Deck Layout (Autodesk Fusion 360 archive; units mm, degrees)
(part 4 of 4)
sketch "Filpper-Straight" plane through (0, 0, 0) normal (0, 0, 1) x axis (1, 0, 0)
  line L1 (-5.745, 3.7993) -> (5.745, 3.7993)
  line L2 (47.7564, -7.9642) -> (0, -12.5)
  line L3 (-5.745, -3.7993) -> (5.745, -3.7993)
  line L4 (47.766, 7.9632) -> (1.1968, 12.4426)
  arc A1 centre (47, 0) radius 8 clockwise from (47.766, 7.9632) to (47.7564, -7.9642)
  circle C1 centre (4.3, 0) radius 1.4
  circle C2 centre (0, 0) radius 6.8
  arc A2 centre (0, 0) radius 12.5 clockwise from (2.3532, -12.2765) to (1.1968, 12.4426)
  circle C3 centre (-4.3, 0) radius 1.4
  point P7 (0, 0)
  point P8 (0, 0)
  point P10 (0, -12.5)
  point P12 (2.3532, -12.2765)
  point P13 (0, 0)
  coincident P7 P8
  coincident P10 A2
  tangent A1 L2
  tangent A2 L4
  tangent A1 L4
  coincident P12 L2
  coincident P7 P13
  dimension "d473" diameter C2 = 13.6
  dimension "d474" diameter C1 = 2.8
  dimension "d475" diameter C3 = 2.8
extrude "Extrude71" new body sketch "Filpper-Straight" profile of C1 C2 L1 C3 L3 blind -31.6 from offset 0.4 bodies "Flipper_Straight"
extrude "Extrude72" cut sketch "Filpper-Straight" profile of C2 L1 L3 blind -19 taper 3 from offset -22.3
extrude "Extrude73" add sketch "Filpper-Straight" blind 25 from offset 0.4
sweep "Sweep3" sketch "Rubber Band profile" TwistAngle 0 TaperAngle 0
extrude "Extrude74" cut sketch "Filpper-Straight" profile of C1 C3 blind -11 from offset -21
extrude "Extrude75" cut sketch "Silicon Chip Logo Flipper" against normal blind 0.4
extrude "Extrude76" new body sketch "Filpper-Straight" blind 25 from offset 0.4 bodies "Flipper Straight + 1"
sweep "Sweep4" sketch "Rubber Band profile" TwistAngle 0 TaperAngle 0
extrude "Extrude77" add sketch "Filpper-Straight" profile of C1 C2 L1 C3 L3 blind -32.6 from offset 0.4
extrude "Extrude78" cut sketch "Filpper-Straight" profile of C2 L1 L3 blind -19 taper 3 from offset -23.3
extrude "Extrude79" cut sketch "Filpper-Straight" profile of C1 C3 blind -19 from offset -22
extrude "Extrude80" cut sketch "Silicon Chip Logo Flipper" against normal blind 0.4
combine "Combine2" bodies "Bushing + 1"
sketch "Sketch38" plane through (0, 0, -31.2) normal (0, 0, -1) x axis (1, 0, 0)
  line L1 (-5.1764, -19.3185) -> (-3.8823, -14.4889)
  line L2 (3.8823, -14.4889) -> (5.1764, -19.3185)
  line L3 (5.1764, 19.3185) -> (3.8823, 14.4889)
  line L4 (-3.8823, 14.4889) -> (-5.1764, 19.3185)
  line L5 (3.3862, 6.2405) -> (-7.0975, 0.1877)
  line L6 (-3.3862, -6.2405) -> (7.0975, -0.1877)
  line L7 (2.2996, -13.1142) -> (0.0947, -9.2951)
  line L8 (1.7266, -13.445) -> (2.2996, -13.1142)
  line L9 (-0.4783, -9.6259) -> (1.7266, -13.445)
  line L10 (-1.905, -10.4496) -> (-0.4783, -9.6259)
  line L11 (-2.2, -9.9386) -> (-1.905, -10.4496)
  line L12 (1.2322, -7.957) -> (-2.2, -9.9386)
  line L13 (1.5272, -8.468) -> (1.2322, -7.957)
  line L14 (0.0947, -9.2951) -> (1.5272, -8.468)
  curve K1 (3.6911, -10.9403) -> (4.8862, -11.3255)
  curve K2 (2.8188, -10.0025) -> (3.6911, -10.9403)
  curve K3 (2.4232, -7.9802) -> (2.8188, -10.0025)
  curve K4 (3.5656, -6.5074) -> (2.4232, -7.9802)
  curve K5 (4.8121, -6.1698) -> (3.5656, -6.5074)
  curve K6 (6.0073, -6.545) -> (4.8121, -6.1698)
  curve K7 (6.9309, -7.5615) -> (6.0073, -6.545)
  curve K8 (7.3455, -8.8935) -> (6.9309, -7.5615)
  curve K9 (7.0468, -10.1155) -> (7.3455, -8.8935)
  curve K10 (6.1496, -10.9899) -> (7.0468, -10.1155)
  curve K11 (4.8862, -11.3255) -> (6.1496, -10.9899)
  line L15 (-9.5357, -4.182) -> (-11.6277, -5.6469)
  line L16 (-9.3162, -4.4955) -> (-9.5357, -4.182)
  line L17 (-11.7736, -6.2162) -> (-9.3162, -4.4955)
  line L18 (-12.1164, -5.7268) -> (-11.7736, -6.2162)
  line L19 (-10.7837, -3.9267) -> (-12.1164, -5.7268)
  curve K12 (-10.5021, -3.5547) -> (-10.7837, -3.9267)
  curve K13 (-10.9876, -3.6998) -> (-10.5021, -3.5547)
  line L20 (-13.1094, -4.3086) -> (-10.9876, -3.6998)
  line L21 (-13.4157, -3.8711) -> (-13.1094, -4.3086)
  line L22 (-10.9583, -2.1504) -> (-13.4157, -3.8711)
  line L23 (-10.7388, -2.4638) -> (-10.9583, -2.1504)
  line L24 (-12.7956, -3.904) -> (-10.7388, -2.4638)
  line L25 (-10.2388, -3.1779) -> (-12.7956, -3.904)
  line L26 (-10.0334, -3.4713) -> (-10.2388, -3.1779)
  line L27 (-11.6277, -5.6469) -> (-10.0334, -3.4713)
  line L28 (-9.7284, -5.9583) -> (-9.2708, -5.6378)
  line L29 (-9.2225, -6.6808) -> (-9.7284, -5.9583)
  line L30 (-9.5108, -6.8827) -> (-9.2225, -6.6808)
  line L31 (-10.2414, -5.8428) -> (-9.5108, -6.8827)
  line L32 (-9.3295, -5.2043) -> (-10.2414, -5.8428)
  curve K14 (-8.6958, -5.4975) -> (-9.3295, -5.2043)
  curve K15 (-8.2332, -5.953) -> (-8.6958, -5.4975)
  curve K16 (-7.9275, -6.7196) -> (-8.2332, -5.953)
  curve K17 (-8.0631, -7.4803) -> (-7.9275, -6.7196)
  curve K18 (-8.6129, -8.0901) -> (-8.0631, -7.4803)
  curve K19 (-9.3876, -8.409) -> (-8.6129, -8.0901)
  curve K20 (-10.1517, -8.3007) -> (-9.3876, -8.409)
  curve K21 (-10.7568, -7.7576) -> (-10.1517, -8.3007)
  curve K22 (-11.0079, -7.2152) -> (-10.7568, -7.7576)
  curve K23 (-11.0039, -6.709) -> (-11.0079, -7.2152)
  curve K24 (-10.7319, -6.2412) -> (-11.0039, -6.709)
  line L33 (-10.446, -6.4783) -> (-10.7319, -6.2412)
  curve K25 (-10.6448, -6.8223) -> (-10.446, -6.4783)
  curve K26 (-10.6523, -7.1773) -> (-10.6448, -6.8223)
  curve K27 (-10.4797, -7.5611) -> (-10.6523, -7.1773)
  curve K28 (-10.1419, -7.8991) -> (-10.4797, -7.5611)
  curve K29 (-9.7797, -8.0364) -> (-10.1419, -7.8991)
  curve K30 (-9.428, -8.0213) -> (-9.7797, -8.0364)
  curve K31 (-8.8678, -7.7689) -> (-9.428, -8.0213)
  curve K32 (-8.3972, -7.2708) -> (-8.8678, -7.7689)
  curve K33 (-8.2993, -6.7113) -> (-8.3972, -7.2708)
  curve K34 (-8.5136, -6.1769) -> (-8.2993, -6.7113)
  curve K35 (-8.8836, -5.8215) -> (-8.5136, -6.1769)
  curve K36 (-9.2708, -5.6378) -> (-8.8836, -5.8215)
  line L34 (-6.6506, -8.3024) -> (-8.818, -9.8201)
  line L35 (-6.4229, -8.6276) -> (-6.6506, -8.3024)
  line L36 (-8.5903, -10.1453) -> (-6.4229, -8.6276)
  line L37 (-8.0234, -10.9549) -> (-8.5903, -10.1453)
  line L38 (-8.3134, -11.158) -> (-8.0234, -10.9549)
  line L39 (-9.6773, -9.2101) -> (-8.3134, -11.158)
  line L40 (-9.3873, -9.0071) -> (-9.6773, -9.2101)
  line L41 (-8.818, -9.8201) -> (-9.3873, -9.0071)
  line L42 (9.489, -8.9635) -> (8.4726, -7.203)
  line L43 (8.9159, -9.2943) -> (9.489, -8.9635)
  line L44 (6.4159, -4.9642) -> (8.9159, -9.2943)
  line L45 (8.0493, -4.0211) -> (6.4159, -4.9642)
  curve K37 (8.7319, -3.6822) -> (8.0493, -4.0211)
  curve K38 (9.3833, -3.5758) -> (8.7319, -3.6822)
  curve K39 (9.9717, -3.7934) -> (9.3833, -3.5758)
  curve K40 (10.4442, -4.3083) -> (9.9717, -3.7934)
  curve K41 (10.6324, -5.4461) -> (10.4442, -4.3083)
  curve K42 (9.5832, -6.5618) -> (10.6324, -5.4461)
  line L46 (8.4726, -7.203) -> (9.5832, -6.5618)
  arc A1 centre (0, 0) radius 15 clockwise from (-3.8823, -14.4889) to (-7.5, 12.9904)
  arc A2 centre (0, 0) radius 20 clockwise from (5.1764, -19.3185) to (-5.1764, -19.3185)
  arc A3 centre (0, 0) radius 15 clockwise from (3.8823, 14.4889) to (3.8823, -14.4889)
  arc A4 centre (0, 0) radius 20 clockwise from (-5.1764, 19.3185) to (5.1764, 19.3185)
  arc A5 centre (0, 0) radius 15 clockwise from (-7.5, 12.9904) to (-3.8823, 14.4889)
  circle C1 centre (-5, 8.6603) radius 5
  arc A6 centre (0, 0) radius 7.1 clockwise from (-3.3862, -6.2405) to (-7.0975, 0.1877)
  arc A7 centre (0, 0) radius 7.1 clockwise from (3.3862, 6.2405) to (7.0975, -0.1877)
combine "Combine1" bodies "Bushing + 1"
extrude "Extrude81" cut sketch "Flipper Drive" profile of C2 C4 C6 C8 along normal blind 20
extrude "Extrude82" cut sketch "Flipper Drive" profile of C2 C4 C6 C8 along normal blind 20
extrude "Extrude85" add sketch "Flipper Drive" profile of L20 L23 L24 L26 A12 A13 C3 C5 A21 blind 3.5 from offset 10
mirror "Mirror6" mirrorStitchTolerance 0.1 bodies "Drive Limiter Mirrored"
extrude "Extrude86" cut sketch "Flipper Drive" profile of L5 L7 L15 L17 L20 L23 L24 L26 A14 A15 A16 C2 C3 C4 C5 C6 C7 C8 C9 along normal blind 3.8
mirror "Mirror7" mirrorStitchTolerance 0.1 bodies "Base and Bushing Mirrored"
extrude "Extrude83" cut sketch "Flipper Drive" profile of L5 L7 L15 L17 L20 L23 L24 L26 A14 A15 A16 C2 C3 C4 C5 C6 C7 C8 C9 along normal blind 3.8
extrude "Extrude84" add sketch "Flipper Drive" profile of L20 L23 L24 L26 A12 A13 C3 C5 A21 blind 3.5 from offset 10
named bodies: "DO NOT USE FLIPPER PROTO", "Washer Upper", "Base and Bushing", "Base Section", "Solenoid 22mm", "Solenoid 37mm", "Flipper Drive", "Washer Lower", "Drive Arm Washer", "Solenoid Coupling 38mm", "Solenoid Coupling 41mm", "Solenoid Coupling 42mm", "Solenoid Coupling 40mm", "Solenoid Coupling 43mm", "Solenoid Coupling 39mm", "Bushing + 1", "Washer 0.6", "Solenoid Coupling 47mm", "Solenoid Coupling 45mm", "Flipper Drive Mirrored", "Flipper_Straight", "Flipper Straight + 1", "Drive Limiter", "Drive Limiter Mirrored", "Base and Bushing Mirrored"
